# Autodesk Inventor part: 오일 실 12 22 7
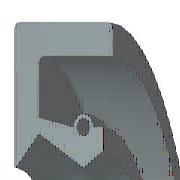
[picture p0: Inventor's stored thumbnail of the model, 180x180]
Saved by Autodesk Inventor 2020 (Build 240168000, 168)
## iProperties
Created: 2012-02
Part Number: 오일 실 12 22 7
Material: 알루미늄 6061
Description: 오일-실
Document SubType Name: Modeling
Standard: KS B 2804
Designer: mduedu
Standards Organization: KS
Language: ko-KR
Size Designation: D - 12 22 7
Categories: <MemberInstance><Categories><Category DisplayName="샤프트 부품" InternalName="7f7aeb1f-a693-4053-b835-cee3144e0d98" Mnemonic="SHFT"><Category DisplayName="실링" Intern
Density: 2.7 g/cm^3
Mass: 3.64014 g
Surface Area: 18.4996 cm^2
Volume: 1.3482 cm^3
Appearance: 알루미늄 - 평지
IsCustomPart: 1
Author: mduedu
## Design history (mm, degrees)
revolve "본체" stored, may be unused: angle "d17" = 90 deg
revolve "스프링1" stored, may be unused: angle "d18" = 90 deg
body "Solid1"
sketch "스케치1"
  geometry: L1 (0, 11)-(7, 11); L2 (7, 9.25)-(1.75, 9.25); L3 (1.75, 7.75)-(4.9, 6); L4 (4.9, 6)-(0, 6); L5 (0, 0)-(9.586, 0) reference; L6 (4.9, 6)-(6.3, 6.875); L7 (0, 18)-(0, -3) reference; L8 (-1.941, 0)-(11.507, 0) reference; L9 (4.2, 8.1)-(1.75, 8.59); L10 (1.75, 8.59)-(1.75, 9.25); L11 (0, 11)-(0, 6.088); L12 (4.9, 6)-(0, 6); L13 (1.75, 7.75)-(0.152, 6.028); L14 (7, 11)-(7, 9.25); L15 (5.6, 8.1)-(6.3, 8.1); L16 (6.3, 8.1)-(6.3, 6.875); C1 r 0.455 at (4.9, 8.1); A1 r 0.7 centre (4.9, 8.1) between (5.6, 8.1) and (4.2, 8.1); A2 r 0.088 centre (0.088, 6.088) between (0, 6.088) and (0.152, 6.028); 1 further point
  constraints: 28 end point, 5 horizontal alignment, 5 point on line, 4 point on circle, 4 vertical alignment, 3 centre point, 3 tangent, 2 collinear, 2 horizontal, 2 perpendicular, 1 coincident, 1 parallel
  dimensions: "d0" = 22 diameter of L1 L5 (= SD2); "d1" = 1.75 distance of L1.end L2.start (= SD); "d2" = 0.91 diameter of C1 (= SPDI); "d3" = 1.4 diameter of A1 (= SPDA); "d4" = 12 diameter of L3.end L5 (= NND); "d5" = 15.5 diameter of L3.start L5 (= TKDM); "d7" = 17.18 diameter of L9.end L5 (= TKDM + 0.24 x SWDT); "d8" = 1.75 distance between parallel lines of L11 L10 (= SD); "d9" = 4.9 distance from line of L11 C1.centre (= SPDST); "d10" = 16.2 diameter of C1.centre L5 (= HLDM); "d11" = 0.0875 radius of A2 (= 0.25 x LAB); "d12" = 6.3 distance between parallel lines of L11 L16 (= SDI); "d13" = 13.75 diameter of L6.end L5 (= ABDM); "d14" = 7 distance from line of L11 L1.end (= SWDT)
fillet "모깎기1" dims "d6" = 0.3 (= RR)
other parameters: "SD2" = 22 [user parameter; used in 1 equation term], "SWDT" = 7 [user parameter; used in 2 equation terms], "RR" = 0.3 [user parameter; used in 1 equation term], "SD" = 1.75 [user parameter; used in 2 equation terms], "NND" = 12 [user parameter; used in 1 equation term], "SPDA" = 1.4 [user parameter; used in 1 equation term], "SPDI" = 0.91 [user parameter; used in 1 equation term], "TKDM" = 15.5 [user parameter; used in 2 equation terms], "HLDM" = 16.2 [user parameter; used in 1 equation term], "ABDM" = 13.75 [user parameter; used in 1 equation term], "SDI" = 6.3 [user parameter; used in 1 equation term], "SPDST" = 4.9 [user parameter; used in 1 equation term], "LAB" = 0.35 [user parameter; used in 1 equation term], "d15" = 0, "d16" = 0, "d19" = 0
